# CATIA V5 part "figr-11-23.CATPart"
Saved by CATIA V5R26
Part number: Part1
Bounding box of the stored display mesh (mm): x -89.703 to 75.958, y -127.286 to 108.862, z -26.487 to 19.815
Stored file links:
  D:\_Deepak\CATIA\CATIA V5-6R2016_Deepak\Resources\Part files\Partfiles\c11_catia_v5_6r2016_prt\figr-11-23.CATPart
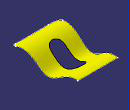
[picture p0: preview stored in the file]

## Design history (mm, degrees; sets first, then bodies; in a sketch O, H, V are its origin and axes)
Set1
  Extrude1: Element1 Sketch3, Lim1 86, Lim2 94, Direction yz-plane
  Sketch1 on xy-plane, origin (0, 0, 0), H (1, 0, 0), V (0, 1, 0)
    line L1 (64.3059, 108.8616) -> (75.9293, -106.0218)
    arc A1 centre (55.7837, -107.1115) radius 20.175 from (75.9293, -106.0218) to (55.7837, -127.2865) cw
    line L2 (55.7837, -127.2865) -> (-64.7868, -127.2865)
    arc A2 centre (-64.7868, -102.3613) radius 24.9252 from (-64.7868, -127.2865) to (-89.6873, -101.2501) cw
    line L3 (-89.6873, -101.2501) -> (-80.3115, 108.8616)
    line L4 (-80.3115, 108.8616) -> (64.3059, 108.8616)
    tangency: A1 L1, A2 L2, A2 L3, A1 L2
    horizontal: L2 H, L4 H
  Extrude2: Element1 Sketch1, Lim1 86, Lim2 94, Direction xy-plane
  Split1: ToCut Extrude1, Cutting Extrude2
  Sketch2 on xy-plane, origin (0, 0, 0), H (1, 0, 0), V (0, 1, 0)
    construction line L1 (-11.3849, 28.4134) -> (-11.3849, -36.9379)
    line L2 (12.8382, 28.4134) -> (12.8382, -36.9379)
    line L3 (-35.608, -36.9379) -> (-35.608, 28.4134)
    arc A1 centre (-11.3849, -36.9379) radius 24.2231 from (12.8382, -36.9379) to (-35.608, -36.9379) cw
    arc A2 centre (-11.3849, 28.4134) radius 24.2231 from (-35.608, 28.4134) to (12.8382, 28.4134) cw
    vertical: L1 V
    tangency: A1 L2, A2 L2, A1 L3, A2 L3
    parallelism: L1 L2
  Extrude3: Element1 Sketch2, Lim1 86, Lim2 94, Direction xy-plane
  Split2: ToCut Split1, Cutting Extrude3
  Boundary1: Boundary edge of Split2, Support Split2
Body1 (main body)
  Sketch3 on yz-plane, origin (0, 0, 0), H (0, 1, 0), V (0, 0, 1)
    spline S1 through (-130.9721, 0) (-85.5087, 19.8151) (-38.0512, 0) (0, -25.6483) (60.0541, -1.7202) (134.7951, -4.3868)
    point P1 (-130.9721, 0)
    point P2 (-38.0512, 0)
    point P3 (0, -25.6483)
    coincidence: P1 H, P2 H, P3 V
